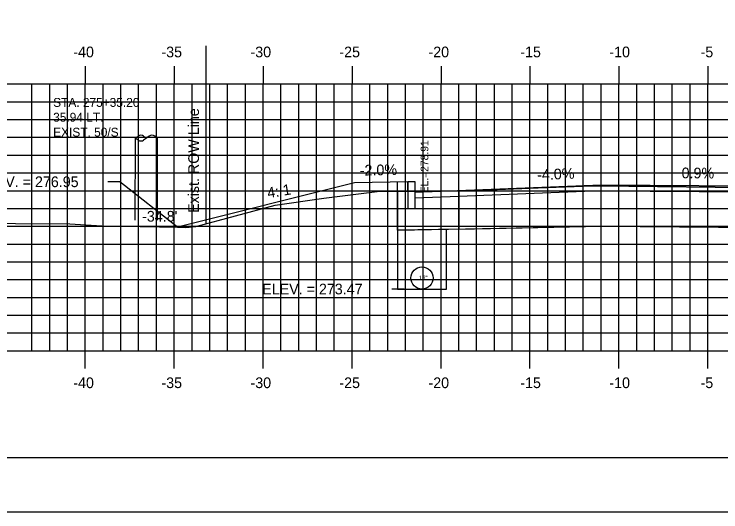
# Model space of a CAD drawing. Extents: x 853563 to 853733, y 366268 to 366378.
# Drawn here: x 853601.77 to 853641.5, y 366268.18 to 366296.16 of the extents above; entities that cross this region are included whole.
import ezdxf

# ---------------------------------------------------------------- set-up
doc = ezdxf.new("R2010")
doc.units = 0
for name, color, linetype in [('ANNOTATION', 7, 'Continuous'), ('BORDER', 7, 'Continuous'), ('D_Curb_Type1_Lt', 7, 'Continuous'), ('D_Roadway_Edge_TW', 7, 'Continuous'), ('D_Roadway_FinishedGrade', 7, 'Continuous'), ('D_Roadway_SubGrade', 7, 'Continuous'), ('D_Text_Monospaced', 7, 'Continuous'), ('D_Text_Standard', 7, 'Continuous'), ('E_ROW_Line', 7, 'Continuous'), ('H_V ANNOTATION', 7, 'Continuous'), ('JUNK COM EXC', 7, 'Continuous'), ('JUNK FILL', 7, 'Continuous'), ('junk strct exc', 7, 'Continuous'), ('MAJOR', 7, 'Continuous'), ('MINOR', 7, 'Continuous'), ('PDRAIN', 7, 'Continuous'), ('PLOT BOUNDARY', 7, 'Continuous'), ('S_Roadway_Centerline', 7, 'Continuous'), ('S_Utilities_Pole_Power', 7, 'Continuous')]:
    doc.layers.add(name, color=color, linetype=linetype)

msp = doc.modelspace()

# ---------------------------------------------------------------- linework, layer by layer
at = {"layer": 'BORDER'}
msp.add_line((853570.768, 366271.236), (853730.768, 366271.236), dxfattribs=at)
at = {"layer": 'D_Curb_Type1_Lt'}
msp.add_lwpolyline([(853623.902, 366286.735), (853623.902, 366285.235), (853624.319, 366285.235), (853624.319, 366286.735)], close=True, dxfattribs=at)
at = {"layer": 'D_Roadway_Edge_TW'}
msp.add_line((853626.768, 366286.249), (853626.773, 366285.916), dxfattribs=at)
msp.add_lwpolyline([(853624.319, 366286.151), (853634.768, 366286.569), (853645.768, 366286.486), (853656.768, 366286.266), (853664.764, 366285.946)], dxfattribs=at)
at = {"layer": 'D_Roadway_FinishedGrade'}
msp.add_line((853620.902, 366286.675), (853610.943, 366284.185), dxfattribs=at)
msp.add_lwpolyline([(853623.902, 366286.735), (853620.902, 366286.675)], dxfattribs=at)
at = {"layer": 'D_Roadway_SubGrade'}
for p, q in [((853623.319, 366284.007), (853623.319, 366286.723)), ((853626.773, 366285.916), (853624.319, 366285.818)), ((853626.773, 366284.076), (853623.319, 366284.007))]:
    msp.add_line(p, q, dxfattribs=at)
for points in [[(853634.773, 366286.236), (853626.773, 366285.916), (853626.773, 366284.076), (853634.773, 366284.236)], [(853634.773, 366284.236), (853634.773, 366286.236), (853645.773, 366286.153), (853656.773, 366285.933), (853656.773, 366283.933), (853645.773, 366284.153)]]:
    msp.add_lwpolyline(points, close=True, dxfattribs=at)
at = {"layer": 'D_Text_Standard'}
for points in [[(853610.943, 366284.185), (853607.717, 366286.736), (853607.037, 366286.736)], [(853623.319, 366280.706), (853623.687, 366280.706), (853623.007, 366280.706)]]:
    msp.add_lwpolyline(points, dxfattribs=at)
at = {"layer": 'E_ROW_Line'}
msp.add_line((853612.558, 366284.383), (853612.558, 366294.383), dxfattribs=at)
at = {"layer": 'JUNK COM EXC'}
msp.add_lwpolyline([(853623.319, 366286.204), (853623.319, 366284.007), (853634.773, 366284.236), (853645.773, 366284.153), (853665.774, 366283.753), (853665.766, 366285.75), (853665.022, 366285.77), (853661.556, 366285.887), (853658.484, 366285.994), (853656.892, 366286.036), (853645.768, 366286.428), (853642.801, 366286.415), (853636.324, 366286.484), (853634.272, 366286.506), (853631.226, 366286.391), (853627.091, 366286.231), (853625.703, 366286.207), (853623.319, 366286.204)], dxfattribs=at)
at = {"layer": 'JUNK FILL'}
msp.add_lwpolyline([(853623.902, 366286.205), (853623.902, 366286.735), (853620.902, 366286.675), (853610.943, 366284.185), (853611.419, 366284.161), (853611.982, 366284.229), (853616.436, 366285.423), (853619.173, 366285.808), (853622.326, 366286.202)], close=True, dxfattribs=at)
at = {"layer": 'junk strct exc'}
msp.add_lwpolyline([(853623.319, 366284.007), (853623.319, 366280.706), (853626.069, 366280.706), (853626.069, 366284.062)], close=True, dxfattribs=at)
at = {"layer": 'MAJOR'}
for p, q in [((853605.768, 366293.238), (853605.768, 366292.236)), ((853610.768, 366293.238), (853610.768, 366292.236)), ((853615.768, 366293.238), (853615.768, 366292.236)), ((853620.768, 366293.238), (853620.768, 366292.236)), ((853625.768, 366293.238), (853625.768, 366292.236)), ((853630.768, 366293.238), (853630.768, 366292.236)), ((853635.768, 366293.238), (853635.768, 366292.236)), ((853640.768, 366293.238), (853640.768, 366292.236)), ((853575.768, 366292.236), (853715.768, 366292.236)), ((853575.768, 366292.236), (853715.768, 366292.236)), ((853605.768, 366277.236), (853605.768, 366292.236)), ((853610.768, 366277.236), (853610.768, 366292.236)), ((853615.768, 366277.236), (853615.768, 366292.236)), ((853620.768, 366277.236), (853620.768, 366292.236)), ((853625.768, 366277.236), (853625.768, 366292.236)), ((853630.768, 366277.236), (853630.768, 366292.236)), ((853635.768, 366277.236), (853635.768, 366292.236)), ((853640.768, 366277.236), (853640.768, 366292.236)), ((853575.768, 366287.236), (853715.768, 366287.236)), ((853575.768, 366282.236), (853715.768, 366282.236)), ((853575.768, 366277.236), (853715.768, 366277.236)), ((853575.768, 366277.236), (853715.768, 366277.236)), ((853605.768, 366276.234), (853605.768, 366277.236)), ((853610.768, 366276.234), (853610.768, 366277.236)), ((853615.768, 366276.234), (853615.768, 366277.236)), ((853620.768, 366276.234), (853620.768, 366277.236)), ((853625.768, 366276.234), (853625.768, 366277.236)), ((853630.768, 366276.234), (853630.768, 366277.236)), ((853635.768, 366276.234), (853635.768, 366277.236)), ((853640.768, 366276.234), (853640.768, 366277.236))]:
    msp.add_line(p, q, dxfattribs=at)
at = {"layer": 'MINOR'}
for p, q in [((853602.768, 366277.236), (853602.768, 366292.236)), ((853603.768, 366277.236), (853603.768, 366292.236)), ((853604.768, 366277.236), (853604.768, 366292.236)), ((853606.768, 366277.236), (853606.768, 366292.236)), ((853607.768, 366277.236), (853607.768, 366292.236)), ((853608.768, 366277.236), (853608.768, 366292.236)), ((853609.768, 366277.236), (853609.768, 366292.236)), ((853611.768, 366277.236), (853611.768, 366292.236)), ((853612.768, 366277.236), (853612.768, 366292.236)), ((853613.768, 366277.236), (853613.768, 366292.236)), ((853614.768, 366277.236), (853614.768, 366292.236)), ((853616.768, 366277.236), (853616.768, 366292.236)), ((853617.768, 366277.236), (853617.768, 366292.236)), ((853618.768, 366277.236), (853618.768, 366292.236)), ((853619.768, 366277.236), (853619.768, 366292.236)), ((853621.768, 366277.236), (853621.768, 366292.236)), ((853622.768, 366277.236), (853622.768, 366292.236)), ((853623.768, 366277.236), (853623.768, 366292.236)), ((853624.768, 366277.236), (853624.768, 366292.236)), ((853626.768, 366277.236), (853626.768, 366292.236)), ((853627.768, 366277.236), (853627.768, 366292.236)), ((853628.768, 366277.236), (853628.768, 366292.236)), ((853629.768, 366277.236), (853629.768, 366292.236)), ((853631.768, 366277.236), (853631.768, 366292.236)), ((853632.768, 366277.236), (853632.768, 366292.236)), ((853633.768, 366277.236), (853633.768, 366292.236)), ((853634.768, 366277.236), (853634.768, 366292.236)), ((853636.768, 366277.236), (853636.768, 366292.236)), ((853637.768, 366277.236), (853637.768, 366292.236)), ((853638.768, 366277.236), (853638.768, 366292.236)), ((853639.768, 366277.236), (853639.768, 366292.236)), ((853575.768, 366291.236), (853715.768, 366291.236)), ((853575.768, 366290.236), (853715.768, 366290.236)), ((853575.768, 366289.236), (853715.768, 366289.236)), ((853575.768, 366288.236), (853715.768, 366288.236)), ((853575.768, 366286.236), (853715.768, 366286.236)), ((853575.768, 366285.236), (853715.768, 366285.236)), ((853575.768, 366284.236), (853715.768, 366284.236)), ((853575.768, 366283.236), (853715.768, 366283.236)), ((853575.768, 366281.236), (853715.768, 366281.236)), ((853575.768, 366280.236), (853715.768, 366280.236)), ((853575.768, 366279.236), (853715.768, 366279.236)), ((853575.768, 366278.236), (853715.768, 366278.236))]:
    msp.add_line(p, q, dxfattribs=at)
at = {"layer": 'PDRAIN'}
msp.add_lwpolyline([(853623.319, 366284.007), (853623.319, 366280.706), (853626.069, 366280.706), (853626.069, 366284.062)], dxfattribs=at)
msp.add_circle((853624.694, 366281.331), 0.625, dxfattribs=at)
at = {"layer": 'PLOT BOUNDARY'}
msp.add_lwpolyline([(853562.674, 366268.177), (853732.674, 366268.177), (853732.674, 366378.177), (853562.674, 366378.177)], close=True, dxfattribs=at)
at = {"layer": 'S_Roadway_Centerline'}
msp.add_lwpolyline([(853598.769, 366284.407), (853604.894, 366284.377), (853606.698, 366284.265), (853611.003, 366284.182), (853611.419, 366284.161), (853611.982, 366284.229), (853616.436, 366285.423), (853619.173, 366285.808), (853622.326, 366286.202), (853625.703, 366286.207), (853627.091, 366286.231), (853631.226, 366286.391), (853634.272, 366286.506), (853636.324, 366286.484), (853642.801, 366286.415), (853645.768, 366286.428), (853656.892, 366286.036), (853658.484, 366285.994), (853661.556, 366285.887), (853665.022, 366285.77), (853671.472, 366285.595), (853672.225, 366285.511), (853672.991, 366285.531), (853684.27, 366285.84)], dxfattribs=at)
at = {"layer": 'S_Utilities_Pole_Power'}
for p, q in [((853608.581, 366289.194), (853608.737, 366289.304)), ((853608.581, 366284.575), (853608.584, 366289.194)), ((853608.737, 366289.083), (853608.581, 366289.194)), ((853609.049, 366289.304), (853609.206, 366289.194)), ((853609.206, 366289.194), (853609.049, 366289.083)), ((853609.362, 366289.304), (853609.206, 366289.194)), ((853609.831, 366289.194), (853609.675, 366289.304)), ((853609.831, 366284.575), (853609.834, 366289.194))]:
    msp.add_line(p, q, dxfattribs=at)
for centre, start, end in [((853608.893, 366289.083), 90, 125.2644), ((853608.893, 366289.304), 234.7356, 270), ((853608.893, 366289.083), 54.7356, 90), ((853608.893, 366289.304), 270, 305.2644), ((853609.518, 366289.083), 90, 125.2644), ((853609.518, 366289.083), 54.7356, 90)]:
    msp.add_arc(centre, 0.271, start, end, dxfattribs=at)

# ---------------------------------------------------------------- texts
at = {"layer": 'ANNOTATION'}
for s, rotation, p in [('-2.0%', 1.1458, (853621.205, 366287.081)), ('-4.0%', 2.2906, (853631.183, 366286.827)), ('0.9%', 359.5646, (853639.291, 366286.935)), ('4: 1', 9.4623, (853616.047, 366285.809))]:
    msp.add_text(s, height=0.6, rotation=rotation, dxfattribs=at).set_placement(p)
at = {"layer": 'D_Text_Monospaced'}
for s, height, p in [('STA. 275+35.20', 0.49998, (853603.962, 366290.949)), ('35.94 LT.', 0.5, (853603.962, 366290.115)), ('EXIST. 50/S', 0.49998, (853603.962, 366289.275))]:
    msp.add_text(s, height=height, dxfattribs=at).set_placement(p)
at = {"layer": 'D_Text_Standard'}
msp.add_text(' EL.=278.91', height=0.4335, rotation=90, dxfattribs=at).set_placement((853625.055, 366285.927))
for s, p in [('ELEV. = 276.95', (853599.749, 366286.436)), ("-34.8'", (853608.962, 366284.498)), ('ELEV. = 273.47', (853615.714, 366280.406))]:
    msp.add_text(s, height=0.6, dxfattribs=at).set_placement(p)
at = {"layer": 'E_ROW_Line'}
msp.add_text('Exist. ROW Line', height=0.6, rotation=90, dxfattribs=at).set_placement((853612.158, 366284.983))
at = {"layer": 'H_V ANNOTATION'}
for s, p in [('-40', (853605.093, 366293.736)), ('-35', (853610.048, 366293.736)), ('-30', (853615.056, 366293.736)), ('-25', (853620.053, 366293.736)), ('-20', (853625.061, 366293.736)), ('-15', (853630.224, 366293.736)), ('-10', (853635.232, 366293.736)), ('-5', (853640.358, 366293.736)), ('-40', (853605.093, 366275.136)), ('-35', (853610.048, 366275.136)), ('-30', (853615.056, 366275.136)), ('-25', (853620.053, 366275.136)), ('-20', (853625.061, 366275.136)), ('-15', (853630.224, 366275.136)), ('-10', (853635.232, 366275.136)), ('-5', (853640.358, 366275.136))]:
    msp.add_text(s, height=0.6, dxfattribs=at).set_placement(p)
at = {"layer": 'PDRAIN'}
msp.add_text('15"', height=0.25, dxfattribs=at).set_placement((853624.507, 366281.206))

doc.saveas('drawing.dxf')
